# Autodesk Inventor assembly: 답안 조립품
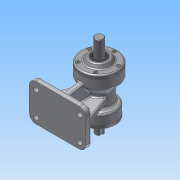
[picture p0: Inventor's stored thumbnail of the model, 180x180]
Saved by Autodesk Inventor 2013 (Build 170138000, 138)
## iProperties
Created: 2015-08
Part Number: 답안 조립품
Document SubType Name: Weldment
Designer: Administrator
Weld Material: Welded Aluminum-6061
Author: Administrator
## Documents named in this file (10)
- C:\Users\Administrator\Desktop\450806V1024\답안 조립품.iam
- C:\Users\Administrator\Desktop\450806V1024\본체.ipt
- C:\Users\Administrator\Desktop\450806V1024\M4x0.5.ipt
- C:\Users\Administrator\Desktop\450806V1024\뒤커버.ipt
- C:\Users\Administrator\Desktop\450806V1024\베어링 6203.ipt
- C:\Users\Administrator\Desktop\450806V1024\베어링 6205.ipt
- C:\Users\Administrator\Desktop\450806V1024\앞커버.ipt
- C:\Users\Administrator\Desktop\450806V1024\오일실 .ipt
- 오일실 .ipt
- C:\Users\Administrator\Desktop\450806V1024\축.ipt
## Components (10 placed, 1 different names)
1. M4x0.5:2
2. M4x0.5:3
3. M4x0.5:4
4. M4x0.5:5
5. M4x0.5:6
6. M4x0.5:1
7. M4x0.5:7
8. M4x0.5:8
9. M4x0.5:9
10. M4x0.5:10
